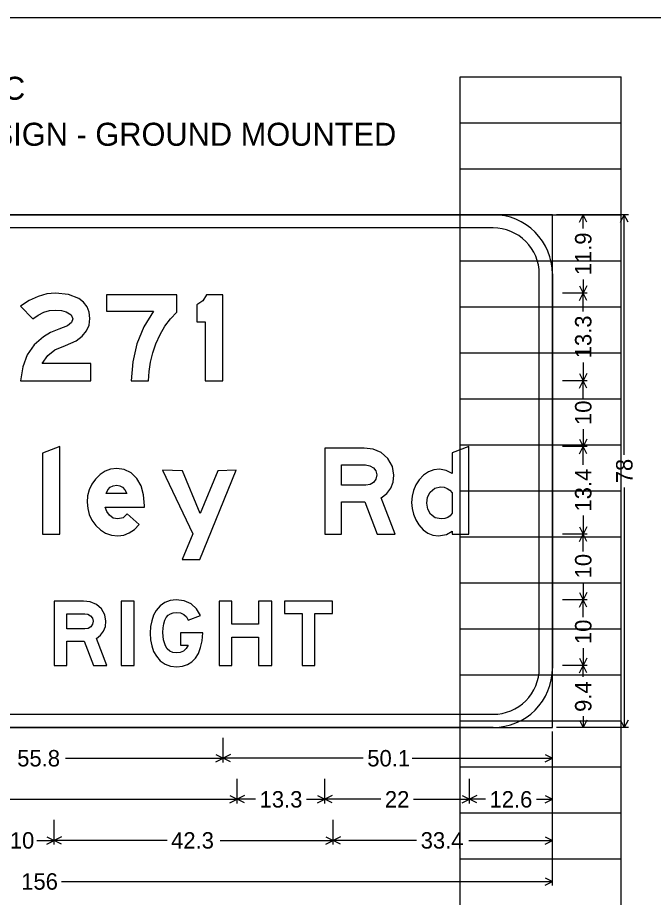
# Model space of a CAD drawing. Extents: x 1820207 to 1820557, y 740216 to 740315.
# Drawn here: x 1820488.52 to 1820492.39, y 740270.39 to 740275.74 of the extents above; entities that cross this region are included whole.
import ezdxf

# ---------------------------------------------------------------- set-up
doc = ezdxf.new("R2010")
doc.units = 0
for name, color, linetype in [('SC_Scratch1', 7, 'Continuous'), ('SC_Scratch2', 7, 'Continuous'), ('SC_Scratch3', 7, 'Continuous'), ('SH_Text', 7, 'Continuous')]:
    doc.layers.add(name, color=color, linetype=linetype)

msp = doc.modelspace()

# ---------------------------------------------------------------- linework, layer by layer
at = {"layer": 'SC_Scratch1'}
for p, q in [((1820491.211, 740255.2219), (1820491.211, 740275.3819)), ((1820491.211, 740275.3819), (1820492.191, 740275.3819)), ((1820492.191, 740255.2219), (1820492.191, 740275.3819)), ((1820491.211, 740275.1019), (1820492.191, 740275.1019)), ((1820491.211, 740274.8219), (1820492.191, 740274.8219)), ((1820491.211, 740274.5419), (1820492.191, 740274.5419)), ((1820491.211, 740274.2619), (1820492.191, 740274.2619)), ((1820491.211, 740273.9819), (1820492.191, 740273.9819)), ((1820491.211, 740273.7019), (1820492.191, 740273.7019)), ((1820491.211, 740273.4219), (1820492.191, 740273.4219)), ((1820491.211, 740273.1419), (1820492.191, 740273.1419)), ((1820491.211, 740272.8619), (1820492.191, 740272.8619)), ((1820491.211, 740272.5819), (1820492.191, 740272.5819)), ((1820491.211, 740272.3019), (1820492.191, 740272.3019)), ((1820491.211, 740272.0219), (1820492.191, 740272.0219)), ((1820491.211, 740271.7419), (1820492.191, 740271.7419)), ((1820491.211, 740271.4619), (1820492.191, 740271.4619)), ((1820491.211, 740271.1819), (1820492.191, 740271.1819)), ((1820491.211, 740270.9019), (1820492.191, 740270.9019)), ((1820491.211, 740270.6219), (1820492.191, 740270.6219))]:
    msp.add_line(p, q, dxfattribs=at)
at = {"layer": 'SC_Scratch2'}
msp.add_lwpolyline([(1820476.451, 740275.7419), (1820506.951, 740275.7419), (1820506.951, 740254.7419), (1820476.451, 740254.7419)], close=True, dxfattribs=at)
at = {"layer": 'SC_Scratch3'}
for p, q in [((1820492.2346, 740274.5419), (1820491.7971, 740274.5419)), ((1820491.9846, 740274.5419), (1820491.8346, 740274.5419)), ((1820491.9372, 740274.4972), (1820491.9596, 740274.5419)), ((1820491.9596, 740274.4584), (1820491.9596, 740274.5419)), ((1820491.982, 740274.4972), (1820491.9596, 740274.5419)), ((1820492.1872, 740274.4972), (1820492.2096, 740274.5419)), ((1820492.2096, 740273.081), (1820492.2096, 740274.5419)), ((1820492.232, 740274.4972), (1820492.2096, 740274.5419)), ((1820491.9596, 740274.1487), (1820491.9596, 740274.0652)), ((1820491.9372, 740274.1099), (1820491.9596, 740274.0652)), ((1820491.982, 740274.1099), (1820491.9596, 740274.0652)), ((1820491.9846, 740274.0652), (1820491.8346, 740274.0652)), ((1820491.9372, 740274.0205), (1820491.9596, 740274.0652)), ((1820491.9596, 740273.9534), (1820491.9596, 740274.0652)), ((1820491.982, 740274.0205), (1820491.9596, 740274.0652)), ((1820491.9596, 740273.6437), (1820491.9596, 740273.5319)), ((1820491.9372, 740273.5766), (1820491.9596, 740273.5319)), ((1820491.982, 740273.5766), (1820491.9596, 740273.5319)), ((1820491.9846, 740273.5319), (1820491.8346, 740273.5319)), ((1820491.9372, 740273.4872), (1820491.9596, 740273.5319)), ((1820491.9596, 740273.4263), (1820491.9596, 740273.5319)), ((1820491.982, 740273.4872), (1820491.9596, 740273.5319)), ((1820491.9596, 740273.2375), (1820491.9596, 740273.1319)), ((1820491.9372, 740273.1766), (1820491.9596, 740273.1319)), ((1820491.982, 740273.1766), (1820491.9596, 740273.1319)), ((1820491.9846, 740273.1319), (1820491.8346, 740273.1319)), ((1820491.9372, 740273.0872), (1820491.9596, 740273.1319)), ((1820491.9596, 740273.0195), (1820491.9596, 740273.1319)), ((1820491.982, 740273.0872), (1820491.9596, 740273.1319)), ((1820492.2096, 740272.8828), (1820492.2096, 740271.4219)), ((1820491.9596, 740272.7109), (1820491.9596, 740272.5986)), ((1820491.9372, 740272.6433), (1820491.9596, 740272.5986)), ((1820491.982, 740272.6433), (1820491.9596, 740272.5986)), ((1820491.9846, 740272.5986), (1820491.8346, 740272.5986)), ((1820491.9372, 740272.5539), (1820491.9596, 740272.5986)), ((1820491.9596, 740272.4929), (1820491.9596, 740272.5986)), ((1820491.982, 740272.5539), (1820491.9596, 740272.5986)), ((1820491.9596, 740272.3042), (1820491.9596, 740272.1986)), ((1820491.9372, 740272.2433), (1820491.9596, 740272.1986)), ((1820491.982, 740272.2433), (1820491.9596, 740272.1986)), ((1820491.9846, 740272.1986), (1820491.8346, 740272.1986)), ((1820491.9372, 740272.1539), (1820491.9596, 740272.1986)), ((1820491.9596, 740272.0929), (1820491.9596, 740272.1986)), ((1820491.982, 740272.1539), (1820491.9596, 740272.1986)), ((1820491.9596, 740271.9042), (1820491.9596, 740271.7986)), ((1820491.9372, 740271.8433), (1820491.9596, 740271.7986)), ((1820491.982, 740271.8433), (1820491.9596, 740271.7986)), ((1820491.9846, 740271.7986), (1820491.8346, 740271.7986)), ((1820491.9846, 740271.7986), (1820491.8346, 740271.7986)), ((1820491.9372, 740271.7539), (1820491.9596, 740271.7986)), ((1820491.9596, 740271.7292), (1820491.9596, 740271.7986)), ((1820491.982, 740271.7539), (1820491.9596, 740271.7986)), ((1820491.9372, 740271.4666), (1820491.9596, 740271.4219)), ((1820491.9596, 740271.4913), (1820491.9596, 740271.4219)), ((1820491.982, 740271.4666), (1820491.9596, 740271.4219)), ((1820492.1872, 740271.4666), (1820492.2096, 740271.4219)), ((1820492.232, 740271.4666), (1820492.2096, 740271.4219)), ((1820492.2346, 740271.4219), (1820491.7971, 740271.4219)), ((1820491.9846, 740271.4219), (1820491.8346, 740271.4219)), ((1820489.7694, 740271.2094), (1820489.7694, 740271.3594)), ((1820489.7694, 740271.2094), (1820489.7694, 740271.3594)), ((1820491.7721, 740270.4594), (1820491.7721, 740271.3969)), ((1820491.7721, 740271.2094), (1820491.7721, 740271.3594)), ((1820489.7247, 740271.2568), (1820489.7694, 740271.2344)), ((1820489.8141, 740271.2568), (1820489.7694, 740271.2344)), ((1820491.7274, 740271.2568), (1820491.7721, 740271.2344)), ((1820488.8117, 740271.2344), (1820489.7694, 740271.2344)), ((1820489.7247, 740271.212), (1820489.7694, 740271.2344)), ((1820490.6214, 740271.2344), (1820489.7694, 740271.2344)), ((1820489.8141, 740271.212), (1820489.7694, 740271.2344)), ((1820490.9201, 740271.2344), (1820491.7721, 740271.2344)), ((1820491.7274, 740271.212), (1820491.7721, 740271.2344)), ((1820489.8548, 740270.9594), (1820489.8548, 740271.1094)), ((1820490.3881, 740270.9594), (1820490.3881, 740271.1094)), ((1820491.2681, 740270.9594), (1820491.2681, 740271.1094)), ((1820491.2681, 740270.9594), (1820491.2681, 740271.1094)), ((1820491.7721, 740270.9594), (1820491.7721, 740271.1094)), ((1820488.105, 740270.9844), (1820489.8548, 740270.9844)), ((1820489.8101, 740271.0068), (1820489.8548, 740270.9844)), ((1820489.8101, 740270.962), (1820489.8548, 740270.9844)), ((1820489.8995, 740271.0068), (1820489.8548, 740270.9844)), ((1820489.9666, 740270.9844), (1820489.8548, 740270.9844)), ((1820489.8995, 740270.962), (1820489.8548, 740270.9844)), ((1820490.2763, 740270.9844), (1820490.3881, 740270.9844)), ((1820490.3434, 740271.0068), (1820490.3881, 740270.9844)), ((1820490.3434, 740270.962), (1820490.3881, 740270.9844)), ((1820490.4328, 740271.0068), (1820490.3881, 740270.9844)), ((1820490.7285, 740270.9844), (1820490.3881, 740270.9844)), ((1820490.4328, 740270.962), (1820490.3881, 740270.9844)), ((1820490.9277, 740270.9844), (1820491.2681, 740270.9844)), ((1820491.2234, 740271.0068), (1820491.2681, 740270.9844)), ((1820491.2234, 740270.962), (1820491.2681, 740270.9844)), ((1820491.3128, 740271.0068), (1820491.2681, 740270.9844)), ((1820491.3647, 740270.9844), (1820491.2681, 740270.9844)), ((1820491.3128, 740270.962), (1820491.2681, 740270.9844)), ((1820491.6755, 740270.9844), (1820491.7721, 740270.9844)), ((1820491.7274, 740271.0068), (1820491.7721, 740270.9844)), ((1820491.7274, 740270.962), (1820491.7721, 740270.9844)), ((1820488.7421, 740270.7094), (1820488.7421, 740270.8594)), ((1820490.4381, 740270.7094), (1820490.4381, 740270.8594)), ((1820490.4381, 740270.7094), (1820490.4381, 740270.8594)), ((1820491.7721, 740270.7094), (1820491.7721, 740270.8594)), ((1820488.6365, 740270.7344), (1820488.7421, 740270.7344)), ((1820488.6974, 740270.7568), (1820488.7421, 740270.7344)), ((1820488.6974, 740270.712), (1820488.7421, 740270.7344)), ((1820488.7868, 740270.7568), (1820488.7421, 740270.7344)), ((1820489.4285, 740270.7344), (1820488.7421, 740270.7344)), ((1820488.7868, 740270.712), (1820488.7421, 740270.7344)), ((1820489.7517, 740270.7344), (1820490.4381, 740270.7344)), ((1820490.3934, 740270.7568), (1820490.4381, 740270.7344)), ((1820490.3934, 740270.712), (1820490.4381, 740270.7344)), ((1820490.4828, 740270.7568), (1820490.4381, 740270.7344)), ((1820490.9463, 740270.7344), (1820490.4381, 740270.7344)), ((1820490.4828, 740270.712), (1820490.4381, 740270.7344)), ((1820491.2639, 740270.7344), (1820491.7721, 740270.7344)), ((1820491.7274, 740270.7568), (1820491.7721, 740270.7344)), ((1820491.7274, 740270.712), (1820491.7721, 740270.7344)), ((1820491.7274, 740270.5068), (1820491.7721, 740270.4844)), ((1820488.7873, 740270.4844), (1820491.7721, 740270.4844)), ((1820491.7274, 740270.462), (1820491.7721, 740270.4844))]:
    msp.add_line(p, q, dxfattribs=at)
for points in [[(1820485.5321, 740271.4219), (1820491.7721, 740271.4219), (1820491.7721, 740274.5419), (1820485.5321, 740274.5419), (1820485.5321, 740271.4219), (1820485.5321, 740271.4219), (1820485.5321, 740271.4219)], [(1820485.8921, 740274.5419), (1820491.4121, 740274.5419)], [(1820491.4121, 740274.4619), (1820485.8921, 740274.4619)], [(1820491.4121, 740274.4619), (1820491.4121, 740274.4619), (1820491.4121, 740274.4619)], [(1820491.6921, 740271.7819), (1820491.6921, 740274.1819)], [(1820491.7721, 740274.1819), (1820491.7721, 740271.7819)], [(1820491.6921, 740271.7819), (1820491.6921, 740271.7819), (1820491.6921, 740271.7819)], [(1820485.8921, 740271.5019), (1820491.4121, 740271.5019)], [(1820491.4121, 740271.4219), (1820485.8921, 740271.4219)]]:
    msp.add_lwpolyline(points, dxfattribs=at)
for points in [[(1820488.5374, 740273.5319), (1820488.9646, 740273.5319), (1820488.9646, 740273.6373), (1820488.6688, 740273.6373), (1820488.7029, 740273.6851), (1820488.7469, 740273.7194), (1820488.8118, 740273.7466), (1820488.8755, 740273.775), (1820488.9121, 740273.8029), (1820488.9383, 740273.8349), (1820488.9541, 740273.8708), (1820488.9594, 740273.9107), (1820488.955, 740273.9488), (1820488.9424, 740273.9819), (1820488.9212, 740274.0098), (1820488.8918, 740274.0327), (1820488.8288, 740274.057), (1820488.7494, 740274.0652), (1820488.6972, 740274.0601), (1820488.6445, 740274.045), (1820488.5911, 740274.0199), (1820488.5374, 740273.9848), (1820488.6118, 740273.908), (1820488.6441, 740273.9316), (1820488.6784, 740273.9484), (1820488.7143, 740273.9585), (1820488.7521, 740273.9619), (1820488.7859, 740273.9592), (1820488.8159, 740273.9518), (1820488.8456, 740273.9337), (1820488.8555, 740273.908), (1820488.8473, 740273.8857), (1820488.8233, 740273.8663), (1820488.7706, 740273.8458), (1820488.7209, 740273.8245), (1820488.6778, 740273.7994), (1820488.6209, 740273.7501), (1820488.5788, 740273.6894), (1820488.5507, 740273.6165)], [(1820489.0601, 740273.9554), (1820489.346, 740273.9554), (1820489.287, 740273.859), (1820489.245, 740273.7564), (1820489.2199, 740273.6473), (1820489.2115, 740273.5319), (1820489.3169, 740273.5319), (1820489.3197, 740273.5886), (1820489.328, 740273.6452), (1820489.3418, 740273.7014), (1820489.3613, 740273.7574), (1820489.3863, 740273.813), (1820489.4157, 740273.8633), (1820489.4494, 740273.9083), (1820489.4873, 740273.9482), (1820489.4873, 740274.055), (1820489.0601, 740274.055)], [(1820489.6605, 740273.5319), (1820489.7676, 740273.5319), (1820489.7676, 740274.055), (1820489.6679, 740274.055), (1820489.6457, 740274.0179), (1820489.6094, 740273.9938), (1820489.6094, 740273.8905), (1820489.6605, 740273.8905)], [(1820488.6708, 740272.5986), (1820488.7762, 740272.5986), (1820488.7762, 740273.1319), (1820488.6708, 740273.0915)], [(1820490.7315, 740272.8192), (1820490.7649, 740272.8459), (1820490.7887, 740272.8779), (1820490.8031, 740272.9153), (1820490.808, 740272.9578), (1820490.799, 740273.0109), (1820490.7723, 740273.058), (1820490.7318, 740273.0947), (1820490.6813, 740273.1164), (1820490.6275, 740273.1216), (1820490.3881, 740273.1216), (1820490.3881, 740272.5986), (1820490.4906, 740272.5986), (1820490.4906, 740272.7953), (1820490.6323, 740272.7953), (1820490.706, 740272.5986), (1820490.8153, 740272.5986)], [(1820491.1622, 740272.5986), (1820491.2641, 740272.5986), (1820491.2641, 740273.1319), (1820491.1622, 740273.0921), (1820491.1622, 740272.9667), (1820491.1257, 740272.9863), (1820491.086, 740272.9931), (1820491.0502, 740272.9891), (1820491.0179, 740272.9771), (1820490.9884, 740272.957), (1820490.9622, 740272.9292), (1820490.942, 740272.8979), (1820490.9276, 740272.8644), (1820490.919, 740272.8285), (1820490.9161, 740272.7904), (1820490.9188, 740272.7535), (1820490.927, 740272.7188), (1820490.9408, 740272.6856), (1820490.9601, 740272.6545), (1820490.9856, 740272.6253), (1820491.014, 740272.6048), (1820491.0451, 740272.5923), (1820491.0792, 740272.5884), (1820491.1276, 740272.5954), (1820491.1622, 740272.6165)], [(1820490.7035, 740272.9584), (1820490.6986, 740272.9332), (1820490.6845, 740272.9133), (1820490.6634, 740272.9003), (1820490.6381, 740272.896), (1820490.4906, 740272.896), (1820490.4906, 740273.0191), (1820490.6358, 740273.0191), (1820490.6618, 740273.0149), (1820490.6837, 740273.0026), (1820490.6985, 740272.9832)], [(1820489.2593, 740272.6578), (1820489.187, 740272.7215), (1820489.1612, 740272.6984), (1820489.1285, 740272.6908), (1820489.102, 740272.6963), (1820489.079, 740272.7132), (1820489.062, 740272.7358), (1820489.0525, 740272.7626), (1820489.2908, 740272.7626), (1820489.2908, 740272.7715), (1820489.2862, 740272.8375), (1820489.2713, 740272.8926), (1820489.2456, 740272.9369), (1820489.2096, 740272.9705), (1820489.1673, 740272.9915), (1820489.1225, 740272.9986), (1820489.0857, 740272.9944), (1820489.0519, 740272.9822), (1820489.0211, 740272.9619), (1820488.9934, 740272.9337), (1820488.9711, 740272.9016), (1820488.9554, 740272.8676), (1820488.9458, 740272.8314), (1820488.9428, 740272.7931), (1820488.946, 740272.7537), (1820488.9557, 740272.7171), (1820488.9721, 740272.683), (1820488.995, 740272.6516), (1820489.0235, 740272.6237), (1820489.0554, 740272.604), (1820489.0904, 740272.5922), (1820489.1285, 740272.5884), (1820489.1652, 740272.5927), (1820489.1993, 740272.6056), (1820489.2305, 740272.6272)], [(1820489.4014, 740272.9883), (1820489.5855, 740272.6011), (1820489.5216, 740272.4447), (1820489.6282, 740272.443), (1820489.8498, 740272.9883), (1820489.737, 740272.9837), (1820489.6304, 740272.724), (1820489.5232, 740272.9837)], [(1820489.1833, 740272.8447), (1820489.0583, 740272.8447), (1820489.0679, 740272.8671), (1820489.0818, 740272.8832), (1820489.1001, 740272.8928), (1820489.1227, 740272.896), (1820489.1421, 740272.8928), (1820489.1586, 740272.8832), (1820489.1722, 740272.8671)], [(1820491.1622, 740272.7251), (1820491.1505, 740272.7101), (1820491.1358, 740272.6994), (1820491.1175, 740272.6929), (1820491.0964, 740272.6908), (1820491.0599, 740272.6983), (1820491.0311, 740272.7205), (1820491.014, 740272.7508), (1820491.0084, 740272.787), (1820491.0135, 740272.8223), (1820491.0294, 740272.8535), (1820491.0563, 740272.8776), (1820491.0909, 740272.8858), (1820491.1134, 740272.8834), (1820491.1329, 740272.8766), (1820491.1491, 740272.8651), (1820491.1622, 740272.8494)], [(1820488.9997, 740271.9641), (1820489.0247, 740271.984), (1820489.0425, 740272.0081), (1820489.0534, 740272.0361), (1820489.057, 740272.068), (1820489.0503, 740272.1078), (1820489.0303, 740272.1432), (1820488.9999, 740272.1707), (1820488.962, 740272.1869), (1820488.9216, 740272.1909), (1820488.7421, 740272.1909), (1820488.7421, 740271.7986), (1820488.819, 740271.7986), (1820488.819, 740271.9461), (1820488.9253, 740271.9461), (1820488.9805, 740271.7986), (1820489.0625, 740271.7986)], [(1820489.1501, 740271.7986), (1820489.2292, 740271.7986), (1820489.2292, 740272.1909), (1820489.1501, 740272.1909)], [(1820489.5107, 740271.9986), (1820489.5107, 740271.9216), (1820489.5578, 740271.9216), (1820489.5446, 740271.9015), (1820489.528, 740271.887), (1820489.508, 740271.8784), (1820489.4848, 740271.8755), (1820489.4634, 740271.8781), (1820489.4452, 740271.8862), (1820489.4302, 740271.8997), (1820489.4183, 740271.9185), (1820489.4067, 740271.9544), (1820489.403, 740272.0001), (1820489.4042, 740272.0285), (1820489.4082, 740272.0531), (1820489.4145, 740272.074), (1820489.4238, 740272.0912), (1820489.4355, 740272.1044), (1820489.4499, 740272.114), (1820489.4668, 740272.1197), (1820489.4864, 740272.1216), (1820489.5107, 740272.1188), (1820489.5306, 740272.1101), (1820489.546, 740272.0957), (1820489.557, 740272.0755), (1820489.6315, 740272.1028), (1820489.6075, 740272.1446), (1820489.575, 740272.1745), (1820489.5337, 740272.1925), (1820489.4835, 740272.1986), (1820489.4468, 740272.1945), (1820489.4144, 740272.1823), (1820489.3864, 740272.162), (1820489.3629, 740272.1338), (1820489.3466, 740272.1042), (1820489.3352, 740272.0715), (1820489.3283, 740272.0355), (1820489.3261, 740271.9963), (1820489.3283, 740271.9554), (1820489.3355, 740271.9183), (1820489.3471, 740271.8849), (1820489.3637, 740271.8553), (1820489.3877, 740271.8271), (1820489.4166, 740271.807), (1820489.45, 740271.7949), (1820489.4882, 740271.7909), (1820489.523, 740271.7941), (1820489.5535, 740271.8039), (1820489.5797, 740271.8201), (1820489.6018, 740271.8428), (1820489.6194, 740271.872), (1820489.6328, 740271.9077), (1820489.6419, 740271.9499), (1820489.6469, 740271.9986)], [(1820489.7461, 740271.7986), (1820489.823, 740271.7986), (1820489.823, 740271.9722), (1820489.9845, 740271.9722), (1820489.9845, 740271.7986), (1820490.0657, 740271.7986), (1820490.0657, 740272.1909), (1820489.9845, 740272.1909), (1820489.9845, 740272.051), (1820489.823, 740272.051), (1820489.823, 740272.1909), (1820489.7461, 740272.1909)], [(1820490.2508, 740271.7986), (1820490.3268, 740271.7986), (1820490.3268, 740272.1154), (1820490.4349, 740272.1154), (1820490.4349, 740272.1909), (1820490.1421, 740272.1909), (1820490.1421, 740272.1154), (1820490.2508, 740272.1154)], [(1820488.9786, 740272.0684), (1820488.975, 740272.0495), (1820488.9644, 740272.0346), (1820488.9485, 740272.0249), (1820488.9296, 740272.0216), (1820488.819, 740272.0216), (1820488.819, 740272.114), (1820488.9279, 740272.114), (1820488.9474, 740272.1108), (1820488.9638, 740272.1016), (1820488.9749, 740272.087)]]:
    msp.add_lwpolyline(points, close=True, dxfattribs=at)
for centre, radius, start, end in [((1820491.4121, 740274.1819), 0.36, 0, 90.0002), ((1820491.4121, 740274.1819), 0.28, 0, 90.0002), ((1820491.4121, 740271.7819), 0.36, 270.0001, 0.0003), ((1820491.4121, 740271.7819), 0.28, 270.0001, 0.0003)]:
    msp.add_arc(centre, radius, start, end, dxfattribs=at)

# ---------------------------------------------------------------- texts
for s, p in [('11.9', (1820492.0096, 740274.1737)), ('13.3', (1820492.0096, 740273.6687)), ('10', (1820492.0096, 740273.2625)), ('78', (1820492.2596, 740272.9078)), ('13.4', (1820492.0096, 740272.7359)), ('10', (1820492.0096, 740272.3292)), ('10', (1820492.0096, 740271.9292)), ('9.4', (1820492.0096, 740271.5163))]:
    msp.add_text(s, height=0.1, rotation=90.0002, dxfattribs=at).set_placement(p)
for s, p in [('55.8', (1820488.5175, 740271.1844)), ('50.1', (1820490.6464, 740271.1844)), ('13.3', (1820489.9916, 740270.9344)), ('22', (1820490.7535, 740270.9344)), ('12.6', (1820491.3897, 740270.9344)), ('10', (1820488.4727, 740270.6844)), ('42.3', (1820489.4535, 740270.6844)), ('33.4', (1820490.9713, 740270.6844)), ('156', (1820488.5419, 740270.4344))]:
    msp.add_text(s, height=0.1, dxfattribs=at).set_placement(p)
at = {"layer": 'SH_Text'}
for s, p in [('SPECIAL-C', (1820487.5774, 740275.2419)), ('LEVEL 2 SIGN - GROUND MOUNTED', (1820487.5774, 740274.9619))]:
    msp.add_text(s, height=0.14, dxfattribs=at).set_placement(p)

doc.saveas('drawing.dxf')
